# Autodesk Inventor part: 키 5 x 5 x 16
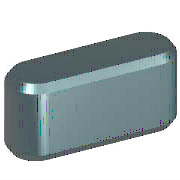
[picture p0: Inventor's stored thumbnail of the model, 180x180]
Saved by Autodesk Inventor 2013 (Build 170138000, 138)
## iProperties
IsCustomPart: 1
Created: 2012-02
Part Number: 키 5 x 5 x 16
Material: 강철, 연강
Description: 키 및 해당 키홈
Document SubType Name: Modeling
Standard: KS B 1311
Designer: mduedu
Standards Organization: KS
Language: ko-KR
Size Designation: 5 x 5 x 16
Categories: <MemberInstance><Categories><Category DisplayName="샤프트 부품" InternalName="7f7aeb1f-a693-4053-b835-cee3144e0d98" Mnemonic="SHFT"><Category DisplayName="키" Interna
Density: 1 g/cm^3
Author: mduedu
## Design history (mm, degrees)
workplane "Work Plane1"
workplane "Work Plane2"
sketch "스케치1"
  geometry: L1 (2.5, 2.5)-(13.5, 2.5); L2 (13.5, -2.5)-(2.5, -2.5); L3 (0, 9.4)-(0, -7.4) reference; L4 (-5, 0)-(30, 0) reference; L5 (16, 0)-(16, 7); A1 r 2.5 centre (2.5, 0) between (2.5, 2.5) and (2.5, -2.5); A2 r 2.5 centre (13.5, 0) between (13.5, -2.5) and (13.5, 2.5)
  constraints: 6 end point, 5 point on circle, 4 tangent, 3 point on line, 2 centre point, 1 horizontal, 1 parallel, 1 perpendicular
  dimensions: "d0" = 2.5 radius of A1 (= 0.5 x PB); "d13" = 2.5 radius of A2 (= 0.5 x PB); "d14" = 16 distance between parallel lines of L5 L3 (= NLG)
extrude "본체1" new body sketch "스케치1" taper "d3" = 0 deg; stored distance "d4" = 10
workplane "Work Plane3"
body "Solid1"
chamfer "모따기1" distance "d8" = 0.4 (= PHH); stored, may be unused: second distance "d9" = 0.4 (= PHH), angle "d15" = 45 deg
other parameters: "d1" = -3 (= -PNT), "d2" = 2 (= PH - PNT), "NLG" = 16 [user parameter; used in 3 equation terms], "PB" = 5 [user parameter; used in 2 equation terms], "PNT" = 3 [user parameter; used in 2 equation terms], "PH" = 5 [user parameter; used in 1 equation term], "PHH" = 0.4 [user parameter; used in 2 equation terms], "d10" = 0, "d16" = 0, "d17" = 0, "d18" = 0, "WDMIN" = 12 [user parameter], "PLB2" = 16 (= NLG) [user parameter], "WDMAX" = 17 [user parameter], "PLB1" = 16 (= NLG) [user parameter], "RR" = 0.16 [user parameter], "PUEB" = 2.3 [user parameter]
